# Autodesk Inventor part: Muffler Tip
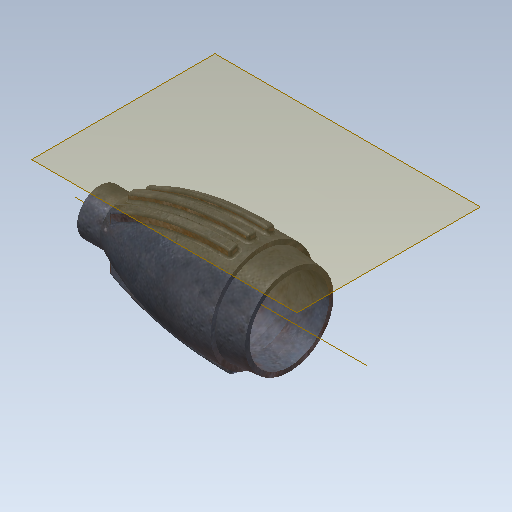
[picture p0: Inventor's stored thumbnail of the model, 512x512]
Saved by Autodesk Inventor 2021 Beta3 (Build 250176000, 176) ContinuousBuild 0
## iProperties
Created: 2012-08
Part Number: Muffler Tip
Material: Aluminum 6061
Document SubType Name: Modeling
Designer: John
Density: 1 g/cm^3
Appearance: Oxidized
Author: John
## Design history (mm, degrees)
sketch "Sketch1"
  geometry: L1 (3.175, 33.073)-(10.795, 33.874); L2 (50.208, 26.971)-(56.558, 26.971); L3 (56.558, 26.971)-(56.558, 20.621); L4 (56.558, 20.621)-(10.795, 20.621); L5 (10.795, 20.621)-(3.175, 20.621); L6 (3.175, 20.621)-(3.175, 33.073); L7 (15.875, 35.144)-(10.795, 35.144); L8 (10.795, 35.144)-(10.795, 33.874); A1 r 76.2 centre (15.875, -41.056) between (50.208, 26.971) and (15.875, 35.144); 1 further point
  constraints: 16 end point, 4 perpendicular, 2 point on circle, 1 centre point, 1 collinear, 1 horizontal, 1 parallel, 1 tangent, 1 other
  dimensions: "d5" = 76.2 radius of A1; "d6" = 6.35 distance of L2.start L2.end; "d7" = 6.35 distance of L2.end L3.end (= d6); "d22" = 5.08 distance of L7.start L7.end; "d23" = 1.27 distance of L7.end L1.end; "d24" = 13.25284 distance from line of L1.end L4; "d25" = 6 deg angle of L7 L1; "d26" = 7.62 distance between parallel lines of L8 L6
revolve "Revolution1" sketch "Sketch1" stored, may be unused: angle "d8" = 90 deg
shell "Shell1" dims "d9" = 1.27
workplane "Work Plane1"
workaxis "Work Axis1"
sketch "Sketch2"
  geometry: L1 (-11.312, 20.621)-(67.869, 20.621) reference; L2 (13.335, 21.891)-(47.668, 21.891); L3 (47.668, 21.891)-(47.668, 19.351); L4 (47.668, 19.351)-(13.335, 19.351); L5 (13.335, 19.351)-(13.335, 21.891); L6 (13.335, 26.971)-(47.668, 26.971); L7 (47.668, 26.971)-(47.668, 24.431); L8 (47.668, 24.431)-(13.335, 24.431); L9 (13.335, 24.431)-(13.335, 26.971); L10 (13.335, 16.811)-(47.668, 16.811); L11 (47.668, 16.811)-(47.668, 14.271); L12 (47.668, 14.271)-(13.335, 14.271); L13 (13.335, 14.271)-(13.335, 16.811); L14 (50.208, 14.271)-(50.208, 26.971) reference; L15 (10.795, 6.098)-(10.795, 35.144) reference; 1 further point
  constraints: 24 end point, 6 collinear, 6 parallel, 3 horizontal, 3 perpendicular
  dimensions: "d11" = 2.54 distance of L2.end L3.end; "d13" = 1.27 distance between parallel lines of L1 L4 (= 0.5 x d11); "d14" = 2.54 distance between parallel lines of L14 L3; "d16" = 2.54 distance between parallel lines of L2 L8; "d17" = 2.54 distance between parallel lines of L4 L10 (= d16); "d27" = 2.54 distance between parallel lines of L15 L9 (= d14)
emboss "Emboss1" sketch "Sketch2" dims "d5" = 76.2, "d6" = 6.35, "d7" = 6.35 (= d6), "d11" = 2.54, "d13" = 1.27 (= 0.5 x d11), "d14" = 2.54, "d16" = 2.54, "d17" = 2.54 (= d16), "d18" = 1.905, "d19" = 0, "d22" = 5.08, "d23" = 1.27, "d24" = 13.25284, "d25" = 6 deg, "d26" = 7.62, "d27" = 2.54 (= d14)
fillet "Fillet1" dims "d20" = 0.635
fillet "Fillet2" dims "d21" = 0.635
mirror "Mirror1"
body "Solid1"
other parameters: "d10" = 19.05
